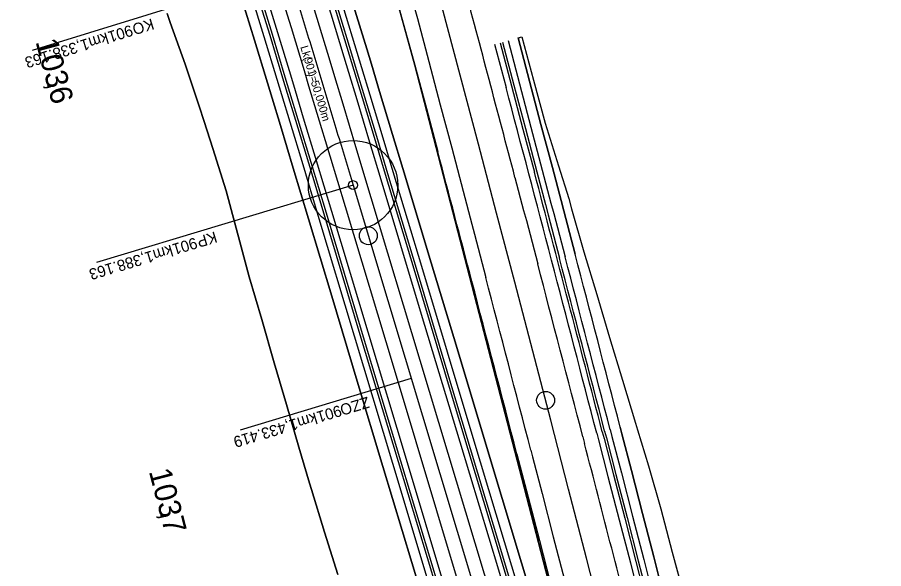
# Model space of a CAD drawing. Extents: x -678487 to -674601, y -1104811 to -1093295.
# Drawn here: x -676260.4 to -676066.4, y -1100339 to -1100215.5 of the extents above; entities that cross this region are included whole.
import ezdxf

# ---------------------------------------------------------------- set-up
doc = ezdxf.new("R2010")
doc.units = 0
for name, color, linetype in [('00_MiNGO', 7, 'Continuous'), ('SOxx02xx_Koleje_hlavní_body_Popis', 7, 'Continuous'), ('SOxx02xx_Koleje_hlavní_body_Popis10', 7, 'Continuous'), ('SOxx02xx_Koleje_LN_staničení_zaoblení_Popis', 7, 'Continuous'), ('SOxx02xx_Koleje_param další_Popis', 7, 'Continuous'), ('SOxx02xx_Staničení_Popis', 7, 'Continuous'), ('SOxx02xx_ŽSp_hrana', 7, 'Continuous'), ('SOxx02xx_ŽSp_odvodnění', 7, 'Continuous'), ('SOxx02xx_ŽSp_zářez_hrana', 7, 'Continuous'), ('SOxx02xx_ŽSp_zářez_plocha', 7, 'Continuous'), ('SOxxxxxx_Osa_bod_P', 7, 'Continuous'), ('SOxxxxxx_Staničení_Popis', 7, 'Continuous'), ('SOxxxxxx_ŽSp_hrana', 7, 'Continuous'), ('SOxxxxxx_ŽSp_násyp_plocha', 7, 'Continuous'), ('SOxxxxxx_ŽSp_odvodnění', 7, 'Continuous'), ('SOxxxxxx_ŽSp_zářez_hrana', 7, 'Continuous'), ('SOxxxxxx_ŽSp_zářez_plocha', 7, 'Continuous')]:
    doc.layers.add(name, color=color, linetype=linetype)

msp = doc.modelspace()

# ---------------------------------------------------------------- linework, layer by layer
at = {"layer": '00_MiNGO'}
for p, q in [((-676171.39, -1100226.25), (-676192.76, -1100149.21)), ((-676122.12, -1100416.22), (-676171.39, -1100226.25))]:
    msp.add_line(p, q, dxfattribs=at)
at = {"layer": 'SOxx02xx_Koleje_hlavní_body_Popis'}
for p, q in [((-676199.76, -1100205.23), (-676257.09, -1100222.93)), ((-676185.24, -1100253.08), (-676242.7, -1100270.37)), ((-676185.24, -1100253.08), (-676185.24, -1100253.08))]:
    msp.add_line(p, q, dxfattribs=at)
msp.add_circle((-676185.24, -1100253.08), 1, dxfattribs=at)
at = {"layer": 'SOxx02xx_Koleje_hlavní_body_Popis10'}
msp.add_line((-676185.24, -1100253.08), (-676185.24, -1100253.08), dxfattribs=at)
msp.add_circle((-676185.24, -1100253.08), 10, dxfattribs=at)
at = {"layer": 'SOxx02xx_Koleje_LN_staničení_zaoblení_Popis'}
msp.add_line((-676172.2, -1100296.41), (-676210.51, -1100307.94), dxfattribs=at)
at = {"layer": 'SOxx02xx_Staničení_Popis'}
msp.add_circle((-676181.83, -1100264.41), 2, dxfattribs=at)
at = {"layer": 'SOxx02xx_ŽSp_hrana'}
for points in [[(-676048.99, -1100695.12), (-676098.21, -1100531.55), (-676121.24, -1100455), (-676132.31, -1100418.23), (-676144.27, -1100378.48), (-676155.78, -1100340.22), (-676170.18, -1100292.38), (-676181.16, -1100255.89), (-676184.59, -1100244.51), (-676187.47, -1100234.94), (-676189.32, -1100228.81), (-676190.37, -1100225.36), (-676193.28, -1100215.79), (-676196.21, -1100206.23), (-676196.84, -1100204.21)], [(-676202.69, -1100206.25), (-676202.07, -1100208.27), (-676199.14, -1100217.82), (-676196.23, -1100227.38), (-676195.19, -1100230.83), (-676193.34, -1100236.94), (-676190.46, -1100246.5), (-676187.04, -1100257.87), (-676176.07, -1100294.31), (-676161.69, -1100342.09), (-676150.19, -1100380.31), (-676138.25, -1100420), (-676127.2, -1100456.73), (-676104.19, -1100533.2), (-676017.42, -1100821.54)]]:
    msp.add_lwpolyline(points, dxfattribs=at)
at = {"layer": 'SOxx02xx_ŽSp_odvodnění'}
for p, q in [((-676206.32, -1100209.75), (-676203.39, -1100219.29)), ((-676203.39, -1100219.29), (-676200.49, -1100228.84)), ((-676200.49, -1100228.84), (-676199.45, -1100232.28)), ((-676199.45, -1100232.28), (-676197.6, -1100238.39)), ((-676197.6, -1100238.39), (-676194.72, -1100247.95)), ((-676194.72, -1100247.95), (-676191.3, -1100259.3)), ((-676191.3, -1100259.3), (-676183.17, -1100286.32)), ((-676183.17, -1100286.32), (-676174.6, -1100314.81)), ((-676174.6, -1100314.81), (-676165.98, -1100343.45))]:
    msp.add_line(p, q, dxfattribs=at)
for points in [[(-676193.35, -1100200.28), (-676192.59, -1100202.73), (-676191.97, -1100204.75), (-676189.03, -1100214.32), (-676186.11, -1100223.9), (-676185.07, -1100227.36), (-676183.21, -1100233.48), (-676180.32, -1100243.07), (-676178.04, -1100250.65), (-676171.67, -1100271.81), (-676163.02, -1100300.55), (-676154.38, -1100329.28), (-676144.29, -1100362.79), (-676136.14, -1100389.87), (-676127.79, -1100417.63)], [(-676192.07, -1100202.55), (-676191.45, -1100204.57), (-676188.51, -1100214.14), (-676185.59, -1100223.72), (-676184.55, -1100227.18), (-676182.69, -1100233.3), (-676179.8, -1100242.89), (-676177.52, -1100250.47), (-676171.15, -1100271.64), (-676162.5, -1100300.38), (-676153.85, -1100329.12), (-676143.77, -1100362.63), (-676135.62, -1100389.71), (-676127.26, -1100417.5)], [(-676207.46, -1100207.91), (-676206.84, -1100209.93), (-676203.91, -1100219.47), (-676201.01, -1100229.02), (-676199.97, -1100232.46), (-676198.12, -1100238.57), (-676195.24, -1100248.12), (-676191.82, -1100259.48), (-676183.7, -1100286.49), (-676175.13, -1100314.98), (-676166.51, -1100343.62), (-676157.89, -1100372.25), (-676149.28, -1100400.88), (-676140.66, -1100429.51), (-676132.05, -1100458.14), (-676123.43, -1100486.78), (-676114.81, -1100515.42), (-676109.06, -1100534.54), (-676103.3, -1100553.68), (-676022.3, -1100822.85)]]:
    msp.add_lwpolyline(points, dxfattribs=at)
at = {"layer": 'SOxx02xx_ŽSp_zářez_hrana'}
for p, q in [((-676226.89, -1100214.68), (-676226.19, -1100216.66)), ((-676226.19, -1100216.66), (-676222.83, -1100226.01)), ((-676222.83, -1100226.01), (-676219.68, -1100235.43)), ((-676219.68, -1100235.43), (-676218.58, -1100238.84)), ((-676218.58, -1100238.84), (-676216.63, -1100244.89)), ((-676216.63, -1100244.89), (-676213.67, -1100254.37)), ((-676213.67, -1100254.37), (-676210.6, -1100265.79)), ((-676210.6, -1100265.79), (-676208.5, -1100273.59)), ((-676208.5, -1100273.59), (-676205.71, -1100283.13)), ((-676205.71, -1100283.13), (-676202.9, -1100292.83)), ((-676202.9, -1100292.83), (-676200.17, -1100302.21)), ((-676200.17, -1100302.21), (-676197.4, -1100311.75)), ((-676197.4, -1100311.75), (-676194.98, -1100319.78)), ((-676194.98, -1100319.78), (-676194.53, -1100321.26)), ((-676194.53, -1100321.26), (-676191.63, -1100330.75)), ((-676191.63, -1100330.75), (-676188.69, -1100340.23))]:
    msp.add_line(p, q, dxfattribs=at)
for points in [[(-676190.86, -1100202.13), (-676190.24, -1100204.15), (-676187.3, -1100213.72), (-676184.38, -1100223.31), (-676183.33, -1100226.76), (-676181.48, -1100232.89), (-676178.59, -1100242.48), (-676176.31, -1100250.06), (-676169.93, -1100271.24), (-676164.17, -1100290.4), (-676158.4, -1100309.57), (-676149.75, -1100338.31), (-676141.1, -1100367.04), (-676132.46, -1100395.77), (-676126.01, -1100417.19)], [(-676188.67, -1100201.37), (-676188.05, -1100203.39), (-676185.11, -1100212.97), (-676182.19, -1100222.55), (-676181.14, -1100226.01), (-676179.29, -1100232.14), (-676176.39, -1100241.73), (-676174.11, -1100249.32), (-676167.73, -1100270.51), (-676161.96, -1100289.68), (-676156.19, -1100308.85), (-676147.54, -1100337.61), (-676138.89, -1100366.35), (-676132.18, -1100388.65), (-676127.35, -1100404.68), (-676123.76, -1100416.63)], [(-676193.8, -1100203.15), (-676193.17, -1100205.17), (-676190.24, -1100214.74), (-676187.32, -1100224.32), (-676186.28, -1100227.77), (-676184.43, -1100233.9), (-676181.54, -1100243.48), (-676179.25, -1100251.06), (-676169.96, -1100281.95), (-676161.36, -1100310.52), (-676152.71, -1100339.25), (-676144.07, -1100367.96), (-676135.43, -1100396.68), (-676129.03, -1100417.94)], [(-676205.73, -1100207.31), (-676205.11, -1100209.33), (-676202.18, -1100218.87), (-676199.28, -1100228.42), (-676198.23, -1100231.87), (-676196.39, -1100237.98), (-676193.51, -1100247.54), (-676190.09, -1100258.89), (-676181.96, -1100285.91), (-676173.38, -1100314.42), (-676164.76, -1100343.06), (-676156.14, -1100371.71), (-676147.53, -1100400.35), (-676138.91, -1100428.99), (-676130.29, -1100457.63), (-676121.67, -1100486.28), (-676110.17, -1100524.49), (-676104.41, -1100543.62), (-676020.53, -1100822.38)], [(-676025.78, -1100823.79), (-676106.77, -1100554.63), (-676112.53, -1100535.5), (-676118.28, -1100516.38), (-676126.89, -1100487.76), (-676132.63, -1100468.68), (-676138.37, -1100449.61), (-676144.11, -1100430.54), (-676149.85, -1100411.46), (-676154.65, -1100395.52), (-676161.33, -1100373.32), (-676169.94, -1100344.7), (-676178.55, -1100316.09), (-676184.29, -1100297), (-676190.03, -1100277.92), (-676195.24, -1100260.63), (-676198.65, -1100249.28), (-676201.53, -1100239.73), (-676203.37, -1100233.63), (-676204.41, -1100230.19), (-676207.32, -1100220.65), (-676210.24, -1100211.11), (-676210.86, -1100209.1)], [(-676023.53, -1100823.19), (-676104.53, -1100554.02), (-676110.29, -1100534.88), (-676116.04, -1100515.76), (-676127.53, -1100477.58), (-676136.15, -1100448.96), (-676144.31, -1100421.82), (-676150.5, -1100401.25), (-676159.12, -1100372.63), (-676167.73, -1100344), (-676176.34, -1100315.37), (-676184.91, -1100286.89), (-676193.04, -1100259.89), (-676196.45, -1100248.53), (-676199.33, -1100238.98), (-676201.18, -1100232.88), (-676202.22, -1100229.43), (-676205.12, -1100219.89), (-676208.05, -1100210.35), (-676208.67, -1100208.34)]]:
    msp.add_lwpolyline(points, dxfattribs=at)
at = {"layer": 'SOxx02xx_ŽSp_zářez_plocha'}
for points in [[(-676192.76, -1100149.21), (-676171.39, -1100226.25), (-676122.12, -1100416.22)], [(-676123.76, -1100416.63), (-676127.35, -1100404.68), (-676132.18, -1100388.65), (-676138.89, -1100366.35), (-676147.54, -1100337.61), (-676156.19, -1100308.85), (-676161.96, -1100289.68), (-676167.73, -1100270.51), (-676174.11, -1100249.32), (-676176.39, -1100241.73), (-676179.29, -1100232.14), (-676181.14, -1100226.01), (-676182.19, -1100222.55), (-676185.11, -1100212.97), (-676188.05, -1100203.39), (-676188.67, -1100201.37)], [(-676210.86, -1100209.1), (-676210.24, -1100211.11), (-676207.32, -1100220.65), (-676204.41, -1100230.19), (-676203.37, -1100233.63), (-676201.53, -1100239.73), (-676198.65, -1100249.28), (-676195.24, -1100260.63), (-676190.03, -1100277.92), (-676184.29, -1100297), (-676178.55, -1100316.09), (-676169.94, -1100344.7), (-676161.33, -1100373.32), (-676154.65, -1100395.52), (-676149.85, -1100411.46), (-676144.11, -1100430.54), (-676138.37, -1100449.61), (-676132.63, -1100468.68), (-676126.89, -1100487.76), (-676118.28, -1100516.38), (-676112.53, -1100535.5), (-676106.77, -1100554.63), (-676042.65, -1100767.7)], [(-676188.69, -1100340.23), (-676191.63, -1100330.75), (-676194.53, -1100321.26), (-676194.98, -1100319.78), (-676197.4, -1100311.75), (-676200.17, -1100302.21), (-676202.9, -1100292.83), (-676205.71, -1100283.13), (-676208.5, -1100273.59), (-676210.6, -1100265.79), (-676213.67, -1100254.37), (-676216.63, -1100244.89), (-676218.58, -1100238.84), (-676219.68, -1100235.43), (-676222.83, -1100226.01), (-676226.19, -1100216.66), (-676226.89, -1100214.68)]]:
    msp.add_lwpolyline(points, dxfattribs=at)
at = {"layer": 'SOxxxxxx_Osa_bod_P'}
msp.add_line((-676185.24, -1100253.08), (-676020.99, -1100798.94), dxfattribs=at)
msp.add_arc((-693563.22, -1104838.51), 18002.25, 14.227837, 20.731742, dxfattribs=at)
msp.add_open_spline([(-676199.76, -1100205.23), (-676198.54, -1100209.21), (-676196.09, -1100217.18), (-676192.46, -1100229.14), (-676188.84, -1100241.11), (-676186.44, -1100249.09), (-676185.24, -1100253.08)], degree=3, dxfattribs=at)
at = {"layer": 'SOxxxxxx_Staničení_Popis'}
for p, q in [((-676181.83, -1100264.41), (-676181.83, -1100264.41)), ((-676142.13, -1100301.26), (-676142.13, -1100301.26))]:
    msp.add_line(p, q, dxfattribs=at)
for centre in [(-676181.83, -1100264.41), (-676142.13, -1100301.26)]:
    msp.add_circle(centre, 2, dxfattribs=at)
at = {"layer": 'SOxxxxxx_ŽSp_hrana'}
msp.add_line((-676133.8, -1100309.43), (-676133.4, -1100310.93), dxfattribs=at)
for points in [[(-676172.2, -1100210.66), (-676170.84, -1100215.77), (-676168.27, -1100225.43), (-676165.71, -1100235.09), (-676163.16, -1100244.76), (-676160.61, -1100254.42), (-676158.67, -1100261.79), (-676158.07, -1100264.09), (-676155.53, -1100273.76)], [(-676148.99, -1100251.36), (-676147.05, -1100258.74), (-676146.44, -1100261.03), (-676143.9, -1100270.71)], [(-676145.43, -1100312.45), (-676145.04, -1100313.95), (-676142.92, -1100322.12), (-676140.41, -1100331.8), (-676137.91, -1100341.48), (-676135.42, -1100351.16), (-676132.93, -1100360.84), (-676131.94, -1100364.67), (-676130.44, -1100370.53), (-676127.96, -1100380.21), (-676125.49, -1100389.9), (-676123.02, -1100399.58), (-676120.56, -1100409.27), (-676119, -1100415.42), (-676118.1, -1100418.96), (-676115.65, -1100428.65), (-676113.2, -1100438.35), (-676110.76, -1100448.04), (-676108.32, -1100457.73), (-676105.88, -1100467.43)]]:
    msp.add_lwpolyline(points, dxfattribs=at)
for radius, start, end in [(18008.26, 14.75728, 14.901402), (18008.26, 14.566318, 14.693626), (17996.24, 14.566318, 14.693626), (18008.26, 14.407183, 14.56137)]:
    msp.add_arc((-693563.22, -1104838.51), radius, start, end, dxfattribs=at)
at = {"layer": 'SOxxxxxx_ŽSp_násyp_plocha'}
msp.add_line((-676133.8, -1100309.43), (-676133.4, -1100310.93), dxfattribs=at)
at = {"layer": 'SOxxxxxx_ŽSp_odvodnění'}
for p, q in [((-676152.31, -1100221.19), (-676149.74, -1100230.86)), ((-676151.78, -1100221.05), (-676149.21, -1100230.72)), ((-676149.74, -1100230.86), (-676147.19, -1100240.54)), ((-676149.21, -1100230.72), (-676146.66, -1100240.4)), ((-676147.19, -1100240.54), (-676144.64, -1100250.21)), ((-676146.66, -1100240.4), (-676144.1, -1100250.07)), ((-676144.1, -1100250.07), (-676142.16, -1100257.45)), ((-676142.16, -1100257.45), (-676141.56, -1100259.75)), ((-676141.56, -1100259.75), (-676139.02, -1100269.43)), ((-676129.44, -1100308.29), (-676129.05, -1100309.8)), ((-676128.91, -1100308.16), (-676128.52, -1100309.66)), ((-676129.05, -1100309.8), (-676126.93, -1100317.98)), ((-676128.52, -1100309.66), (-676126.39, -1100317.84)), ((-676126.93, -1100317.98), (-676124.42, -1100327.66)), ((-676126.39, -1100317.84), (-676123.89, -1100327.53)), ((-676124.42, -1100327.66), (-676121.92, -1100337.35)), ((-676123.89, -1100327.53), (-676121.38, -1100337.22)), ((-676121.92, -1100337.35), (-676119.42, -1100347.04)), ((-676121.38, -1100337.22), (-676118.89, -1100346.9))]:
    msp.add_line(p, q, dxfattribs=at)
for radius, end in [(18012.76, 14.75728), (18013.31, 14.693626)]:
    msp.add_arc((-693563.22, -1104838.51), radius, 14.566318, end, dxfattribs=at)
at = {"layer": 'SOxxxxxx_ŽSp_zářez_hrana'}
for p, q in [((-676153.54, -1100221.52), (-676150.98, -1100231.19)), ((-676150.54, -1100220.72), (-676147.98, -1100230.4)), ((-676148.3, -1100220.13), (-676145.73, -1100229.8)), ((-676147.45, -1100219.9), (-676144.87, -1100229.58)), ((-676171.39, -1100226.25), (-676168.83, -1100235.91)), ((-676147.98, -1100230.4), (-676145.42, -1100240.07)), ((-676145.73, -1100229.8), (-676143.18, -1100239.48)), ((-676144.87, -1100229.58), (-676142.23, -1100239.23)), ((-676168.83, -1100235.91), (-676166.27, -1100245.58)), ((-676145.42, -1100240.07), (-676142.87, -1100249.75)), ((-676143.18, -1100239.48), (-676140.62, -1100249.16)), ((-676142.23, -1100239.23), (-676139.21, -1100248.78)), ((-676139.21, -1100248.78), (-676136.94, -1100256.08)), ((-676142.87, -1100249.75), (-676140.92, -1100257.13)), ((-676140.62, -1100249.16), (-676138.68, -1100256.54)), ((-676138.68, -1100256.54), (-676138.08, -1100258.84)), ((-676136.94, -1100256.08), (-676136.3, -1100258.37)), ((-676140.92, -1100257.13), (-676140.32, -1100259.42)), ((-676136.3, -1100258.37), (-676133.58, -1100268)), ((-676140.32, -1100259.42), (-676137.78, -1100269.1)), ((-676138.08, -1100258.84), (-676135.54, -1100268.52)), ((-676133.58, -1100268), (-676130.68, -1100277.59)), ((-676130.68, -1100277.59), (-676127.79, -1100287.18)), ((-676127.79, -1100287.18), (-676124.89, -1100296.77)), ((-676124.89, -1100296.77), (-676121.98, -1100306.35)), ((-676121.98, -1100306.35), (-676121.52, -1100307.84)), ((-676130.68, -1100308.62), (-676130.29, -1100310.12)), ((-676127.67, -1100307.83), (-676127.28, -1100309.34)), ((-676125.42, -1100307.25), (-676125.03, -1100308.76)), ((-676125.03, -1100308.76), (-676122.91, -1100316.94)), ((-676121.52, -1100307.84), (-676119.07, -1100315.94)), ((-676130.29, -1100310.12), (-676128.17, -1100318.3)), ((-676127.28, -1100309.34), (-676125.16, -1100317.52)), ((-676148.55, -1100313.26), (-676148.16, -1100314.76)), ((-676148.16, -1100314.76), (-676146.04, -1100322.93)), ((-676119.07, -1100315.94), (-676116.35, -1100325.58)), ((-676128.17, -1100318.3), (-676125.66, -1100327.99)), ((-676125.16, -1100317.52), (-676122.65, -1100327.21)), ((-676122.91, -1100316.94), (-676120.4, -1100326.63)), ((-676146.04, -1100322.93), (-676143.53, -1100332.61)), ((-676116.35, -1100325.58), (-676113.76, -1100335.25)), ((-676125.66, -1100327.99), (-676123.15, -1100337.67)), ((-676122.65, -1100327.21), (-676120.14, -1100336.9)), ((-676120.4, -1100326.63), (-676117.9, -1100336.32)), ((-676143.53, -1100332.61), (-676141.03, -1100342.29)), ((-676113.76, -1100335.25), (-676111.17, -1100344.92)), ((-676123.15, -1100337.67), (-676120.66, -1100347.36)), ((-676120.14, -1100336.9), (-676117.65, -1100346.59)), ((-676117.9, -1100336.32), (-676115.4, -1100346.01))]:
    msp.add_line(p, q, dxfattribs=at)
for radius, start, end in [(18011.48, 14.566318, 14.820934), (17993.02, 14.693626, 14.789107), (18014.59, 14.566318, 14.693626), (18016.91, 14.566318, 14.693626), (17993.02, 14.566318, 14.693626)]:
    msp.add_arc((-693563.22, -1104838.51), radius, start, end, dxfattribs=at)
at = {"layer": 'SOxxxxxx_ŽSp_zářez_plocha'}
msp.add_line((-676148.3, -1100220.13), (-676147.45, -1100219.9), dxfattribs=at)
for points in [[(-676135.54, -1100268.52), (-676138.08, -1100258.84), (-676138.68, -1100256.54), (-676140.62, -1100249.16), (-676143.18, -1100239.48), (-676145.73, -1100229.8), (-676148.3, -1100220.13)], [(-676147.45, -1100219.9), (-676144.87, -1100229.58), (-676142.23, -1100239.23), (-676139.21, -1100248.78), (-676136.94, -1100256.08), (-676136.3, -1100258.37), (-676133.58, -1100268), (-676130.68, -1100277.59), (-676127.79, -1100287.18), (-676124.89, -1100296.77), (-676121.98, -1100306.35), (-676121.52, -1100307.84), (-676119.07, -1100315.94), (-676116.35, -1100325.58), (-676113.76, -1100335.25), (-676111.17, -1100344.92)], [(-676083.4, -1100472.1), (-676085.83, -1100462.4), (-676088.27, -1100452.7), (-676090.71, -1100442.99), (-676093.16, -1100433.29), (-676095.61, -1100423.59), (-676098.06, -1100413.88), (-676098.96, -1100410.34), (-676100.52, -1100404.18), (-676102.99, -1100394.48), (-676105.46, -1100384.79), (-676107.94, -1100375.09), (-676110.42, -1100365.39), (-676111.92, -1100359.53), (-676112.91, -1100355.7), (-676115.4, -1100346.01), (-676117.9, -1100336.32), (-676120.4, -1100326.63), (-676122.91, -1100316.94), (-676125.03, -1100308.76), (-676125.42, -1100307.25)]]:
    msp.add_lwpolyline(points, dxfattribs=at)
msp.add_arc((-693563.22, -1104838.51), 18016.91, 14.566318, 14.693626, dxfattribs=at)

# ---------------------------------------------------------------- texts
at = {"layer": 'SOxx02xx_Koleje_hlavní_body_Popis'}
for s, rotation, p in [('KO', 197.1565, (-676230.3, -1100215.71)), ('901', 197.1565, (-676235.02, -1100217.16)), (' km ', 197.1565, (-676239.58, -1100218.57)), ('1,338.163', 197.1565, (-676244.75, -1100220.17)), ('KP', 196.7473, (-676216.16, -1100263.42)), ('901', 196.7473, (-676220.58, -1100264.75)), ('1,388.163', 196.7473, (-676230.34, -1100267.69)), (' km ', 196.7473, (-676225.15, -1100266.13))]:
    msp.add_text(s, height=2.5, rotation=rotation, dxfattribs=at).set_placement(p)
at = {"layer": 'SOxx02xx_Koleje_LN_staničení_zaoblení_Popis'}
for s, p in [('ZZO', (-676182.01, -1100300.41)), ('901', (-676188.26, -1100302.29)), (' km ', (-676192.83, -1100303.67)), ('1,433.419', (-676198.01, -1100305.23))]:
    msp.add_text(s, height=2.5, rotation=196.7473, dxfattribs=at).set_placement(p)
at = {"layer": 'SOxx02xx_Koleje_param další_Popis'}
for s, p in [('Lk(', (-676197.09, -1100222.14)), ('901', (-676196.26, -1100224.88)), (')=', (-676195.26, -1100228.17)), ('50,000m', (-676194.71, -1100229.98))]:
    msp.add_text(s, height=1.8, rotation=286.8496, dxfattribs=at).set_placement(p)
at = {"layer": 'SOxxxxxx_Staničení_Popis'}
for s, rotation, p in [('103', 284.9164, (-676256.38, -1100220.93)), (',', 284.9164, (-676253.92, -1100230.16)), ('6', 284.9164, (-676253.51, -1100231.71)), ('103', 284.5981, (-676231, -1100317.14)), (',', 284.5981, (-676228.59, -1100326.39)), ('7', 284.5981, (-676228.19, -1100327.93))]:
    msp.add_text(s, height=5, rotation=rotation, dxfattribs=at).set_placement(p)

doc.saveas('drawing.dxf')
